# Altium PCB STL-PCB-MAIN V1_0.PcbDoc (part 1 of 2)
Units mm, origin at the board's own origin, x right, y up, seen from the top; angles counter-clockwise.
Board outline 48 x 35.2 mm, 4 copper layers (Top Layer, Int1 (GND), Int4 (PWR), Bottom Layer), stack 0.969 mm thick; 79 components, 63 nets, 420 pads, 232 vias.
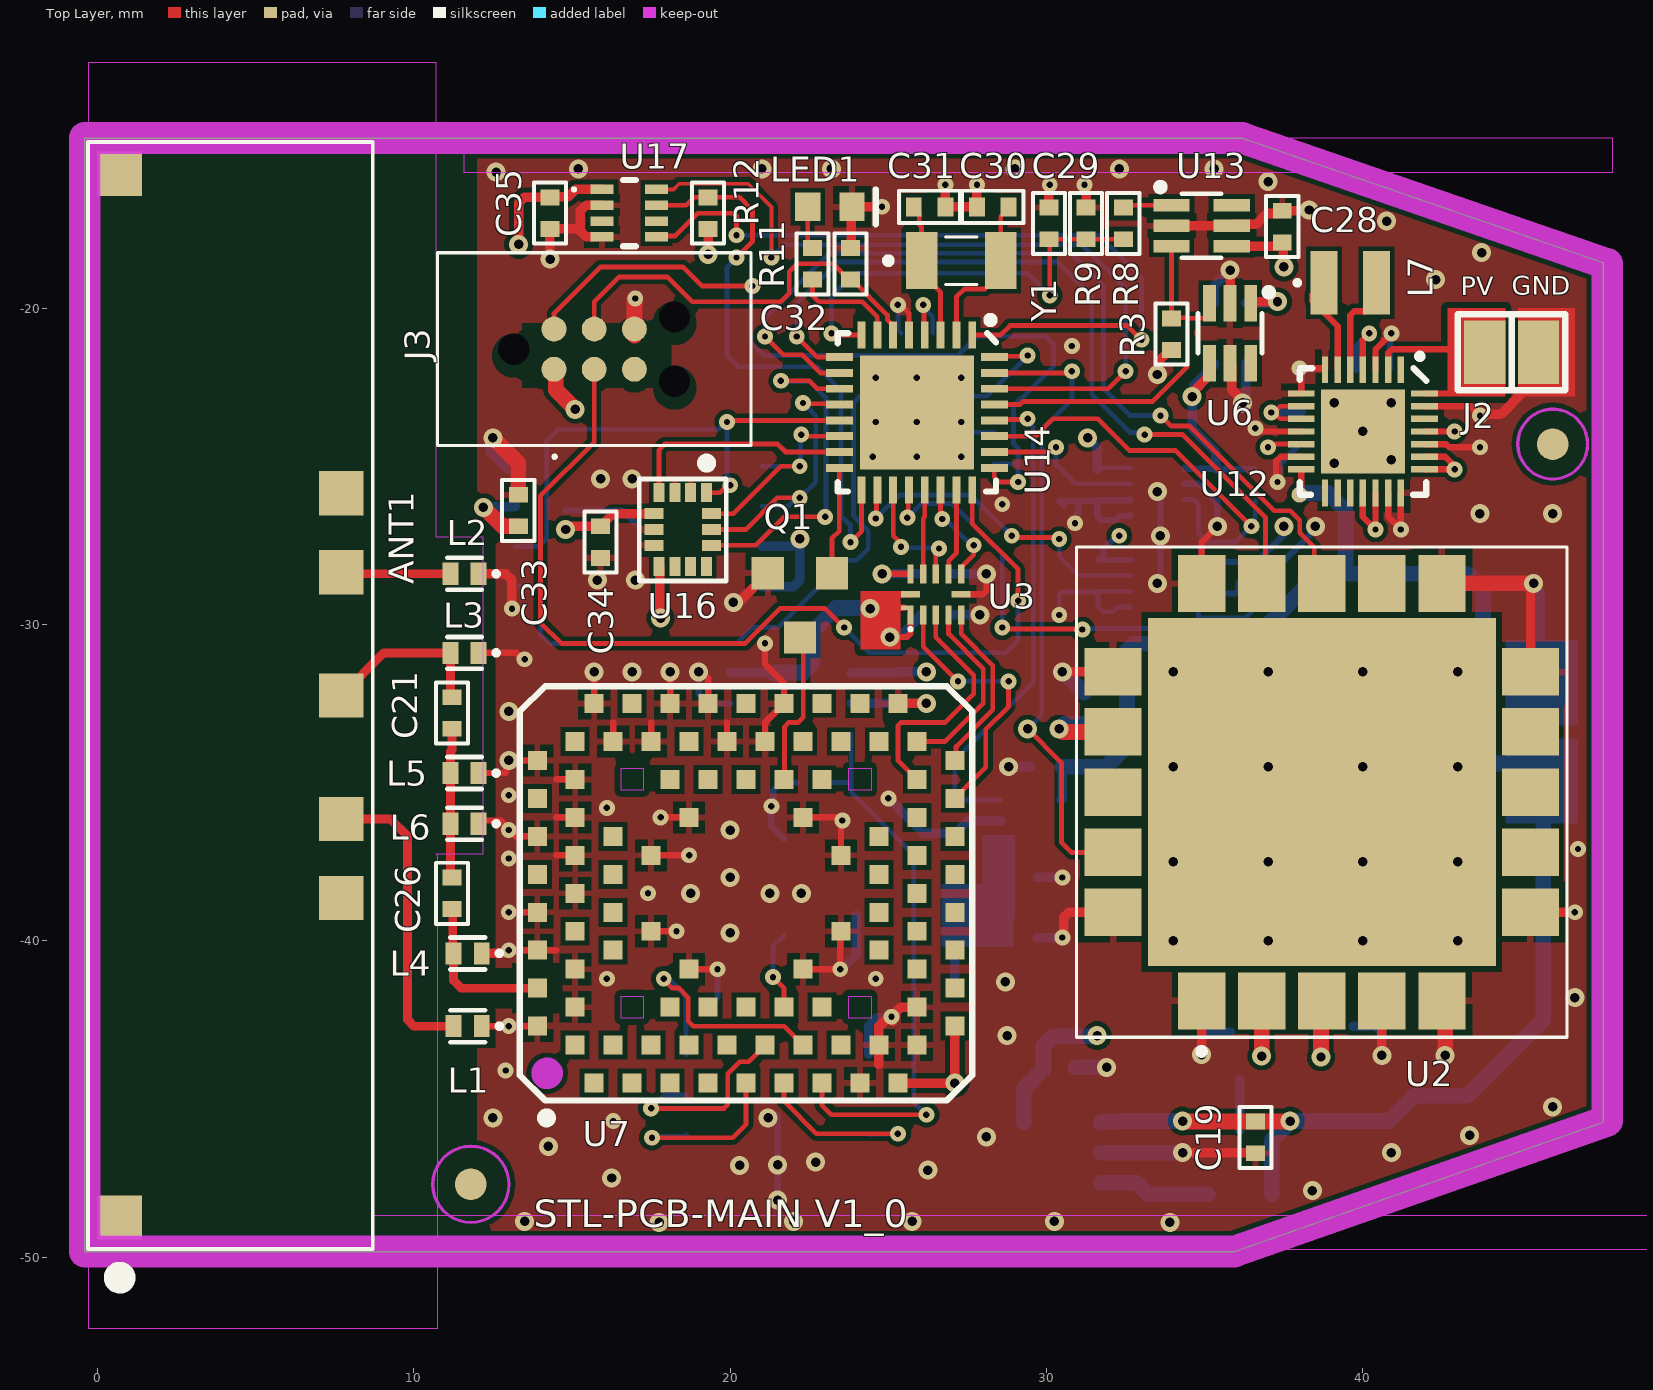
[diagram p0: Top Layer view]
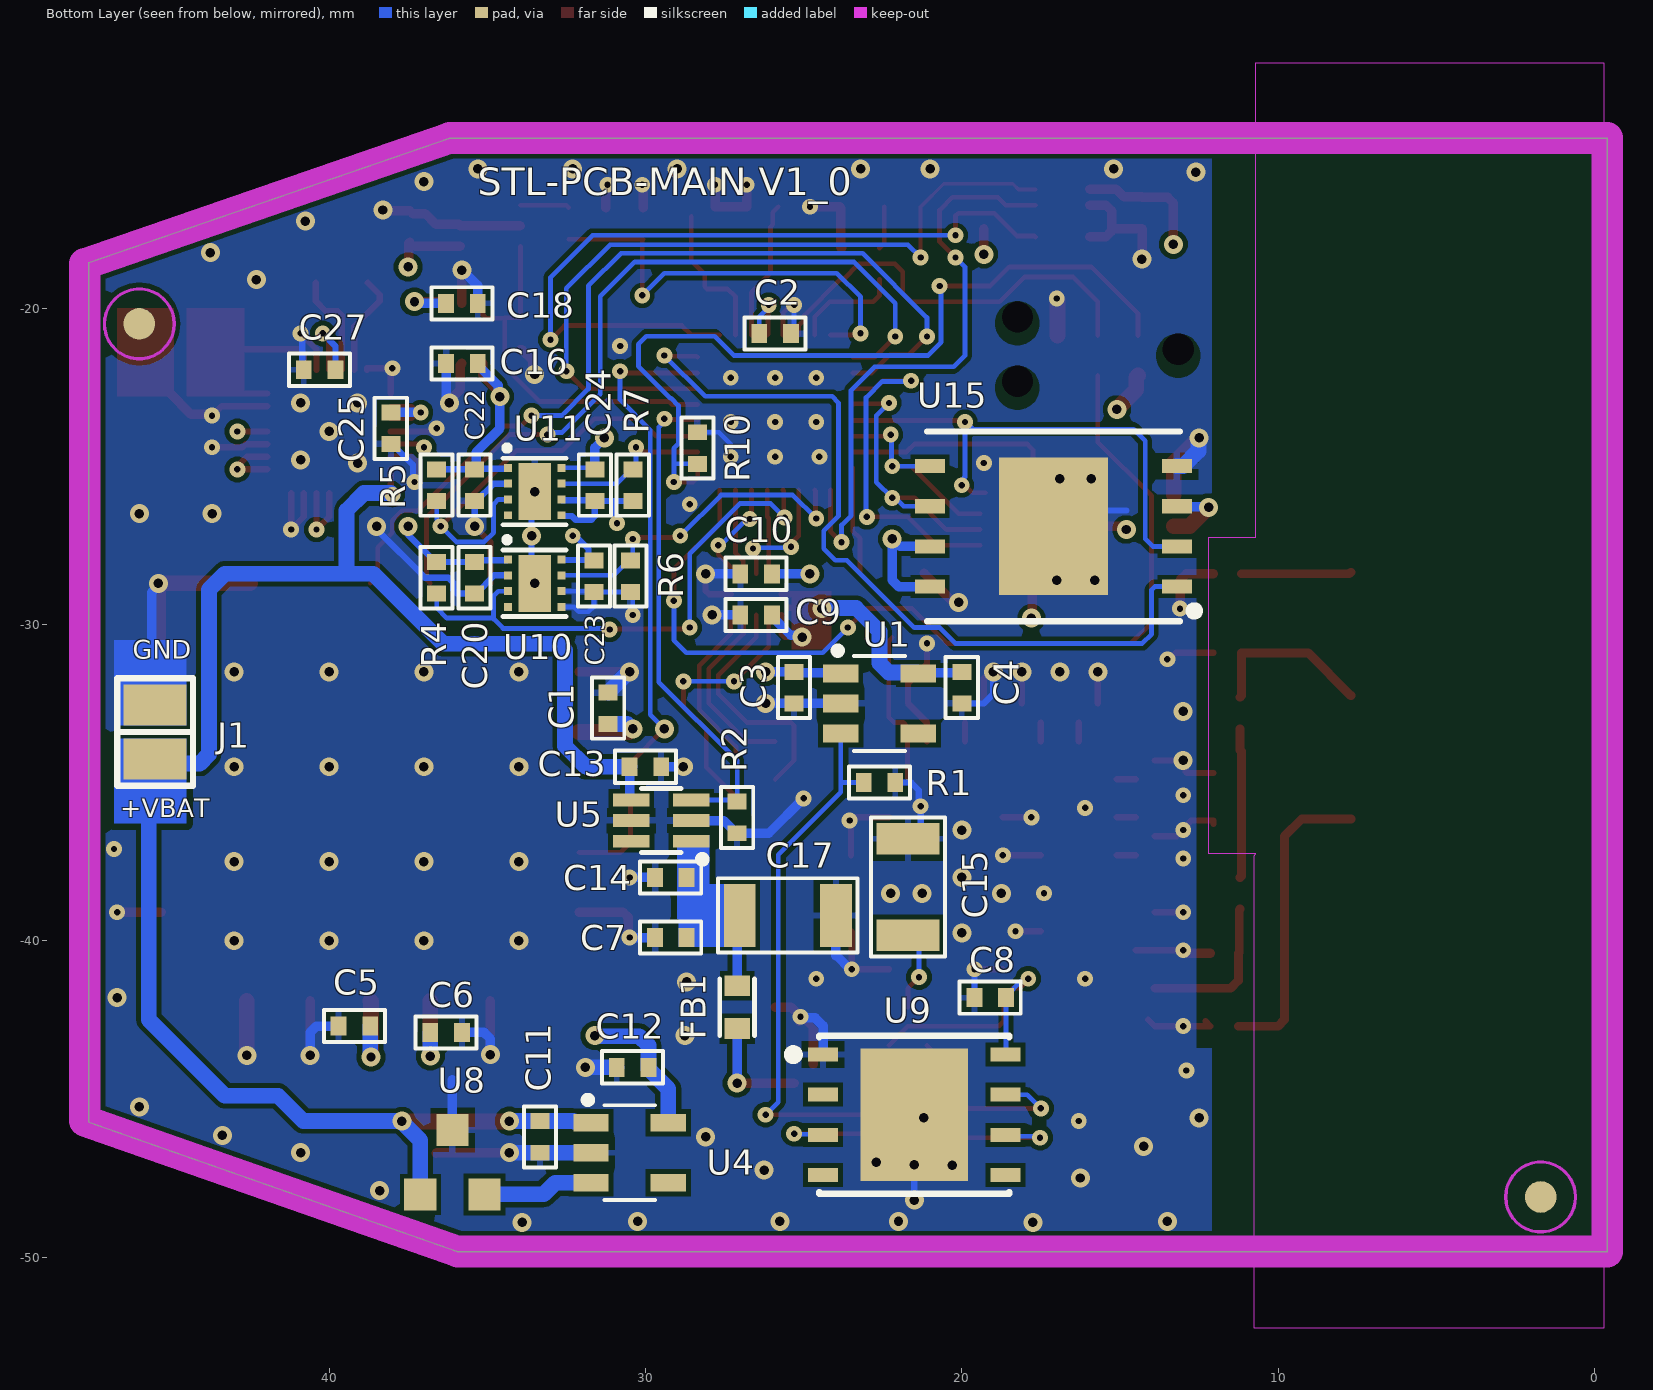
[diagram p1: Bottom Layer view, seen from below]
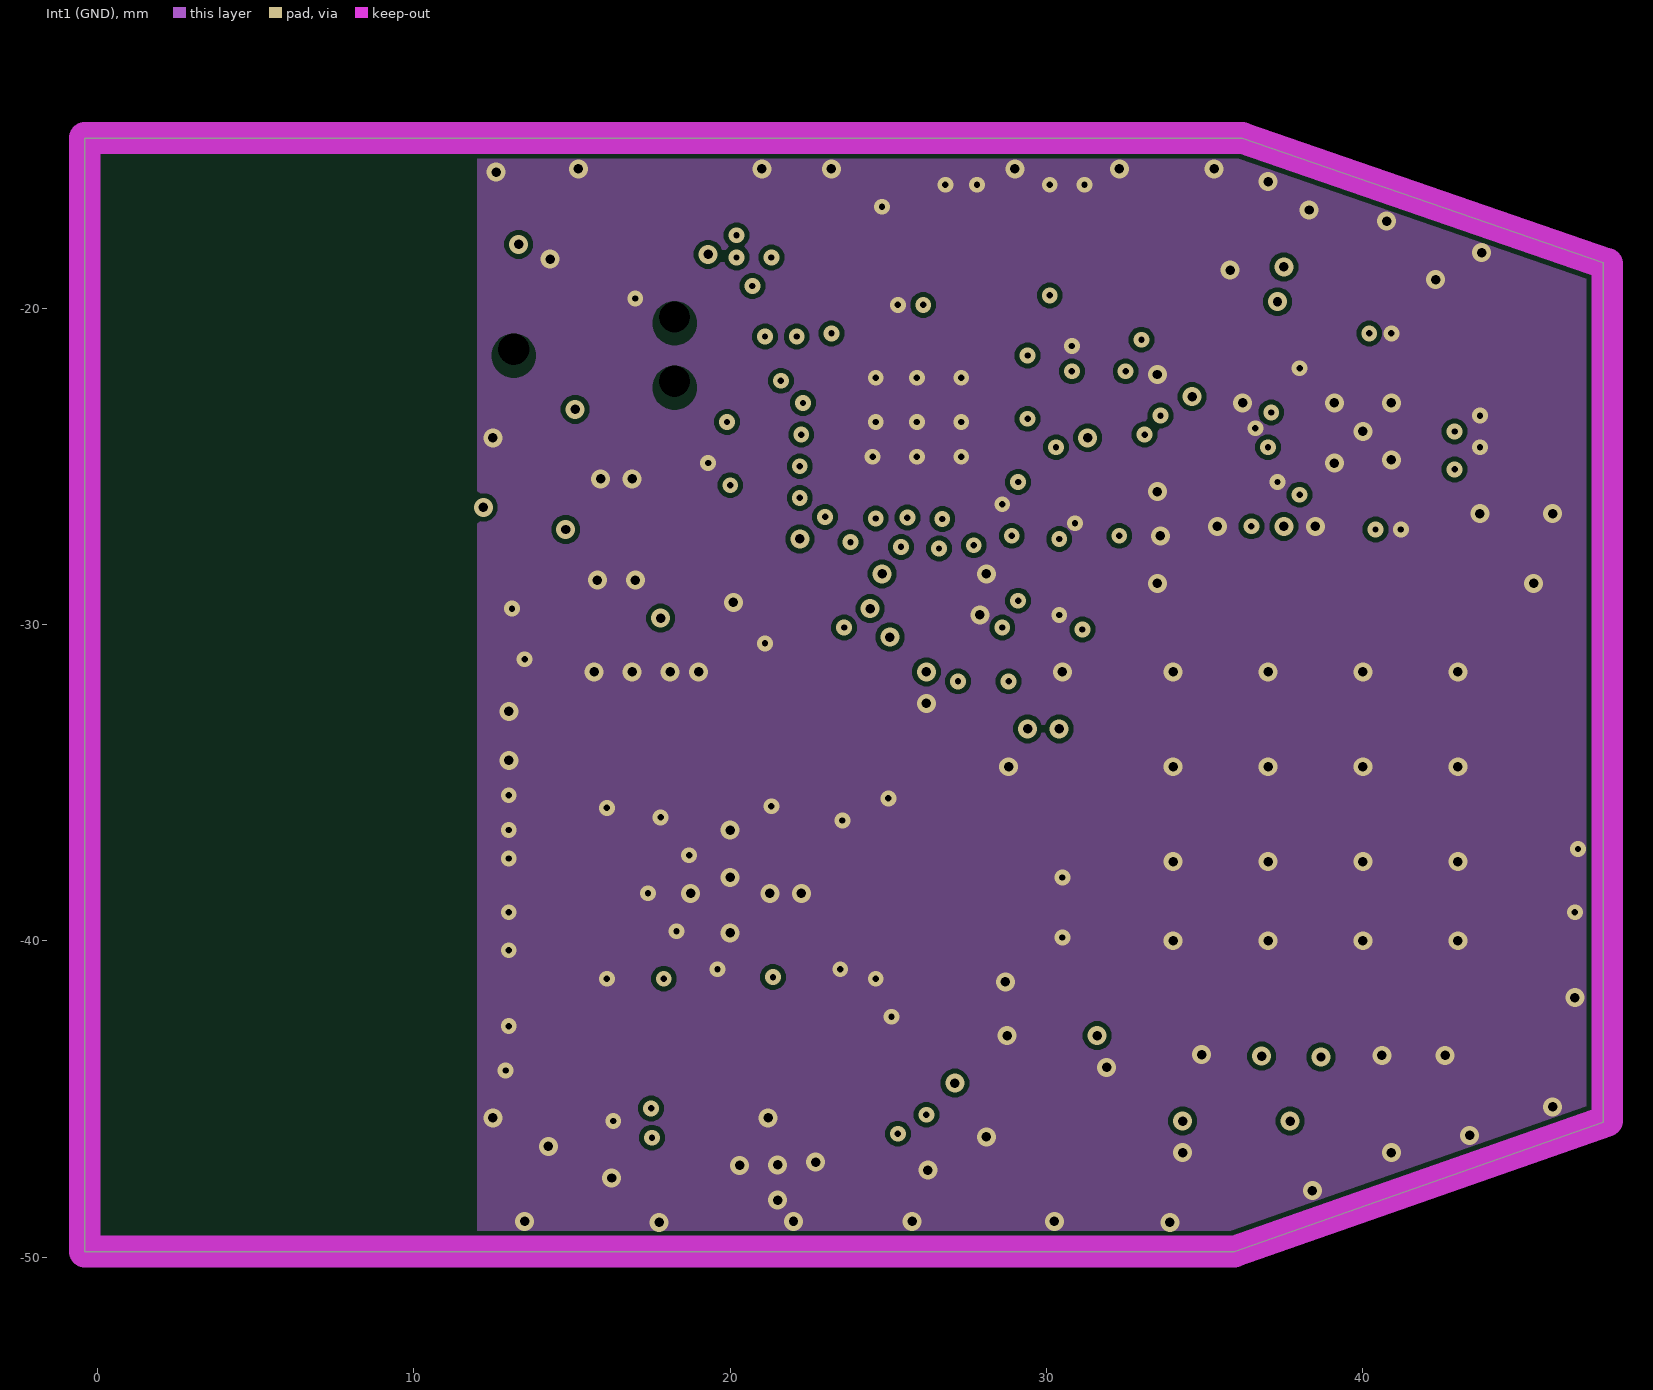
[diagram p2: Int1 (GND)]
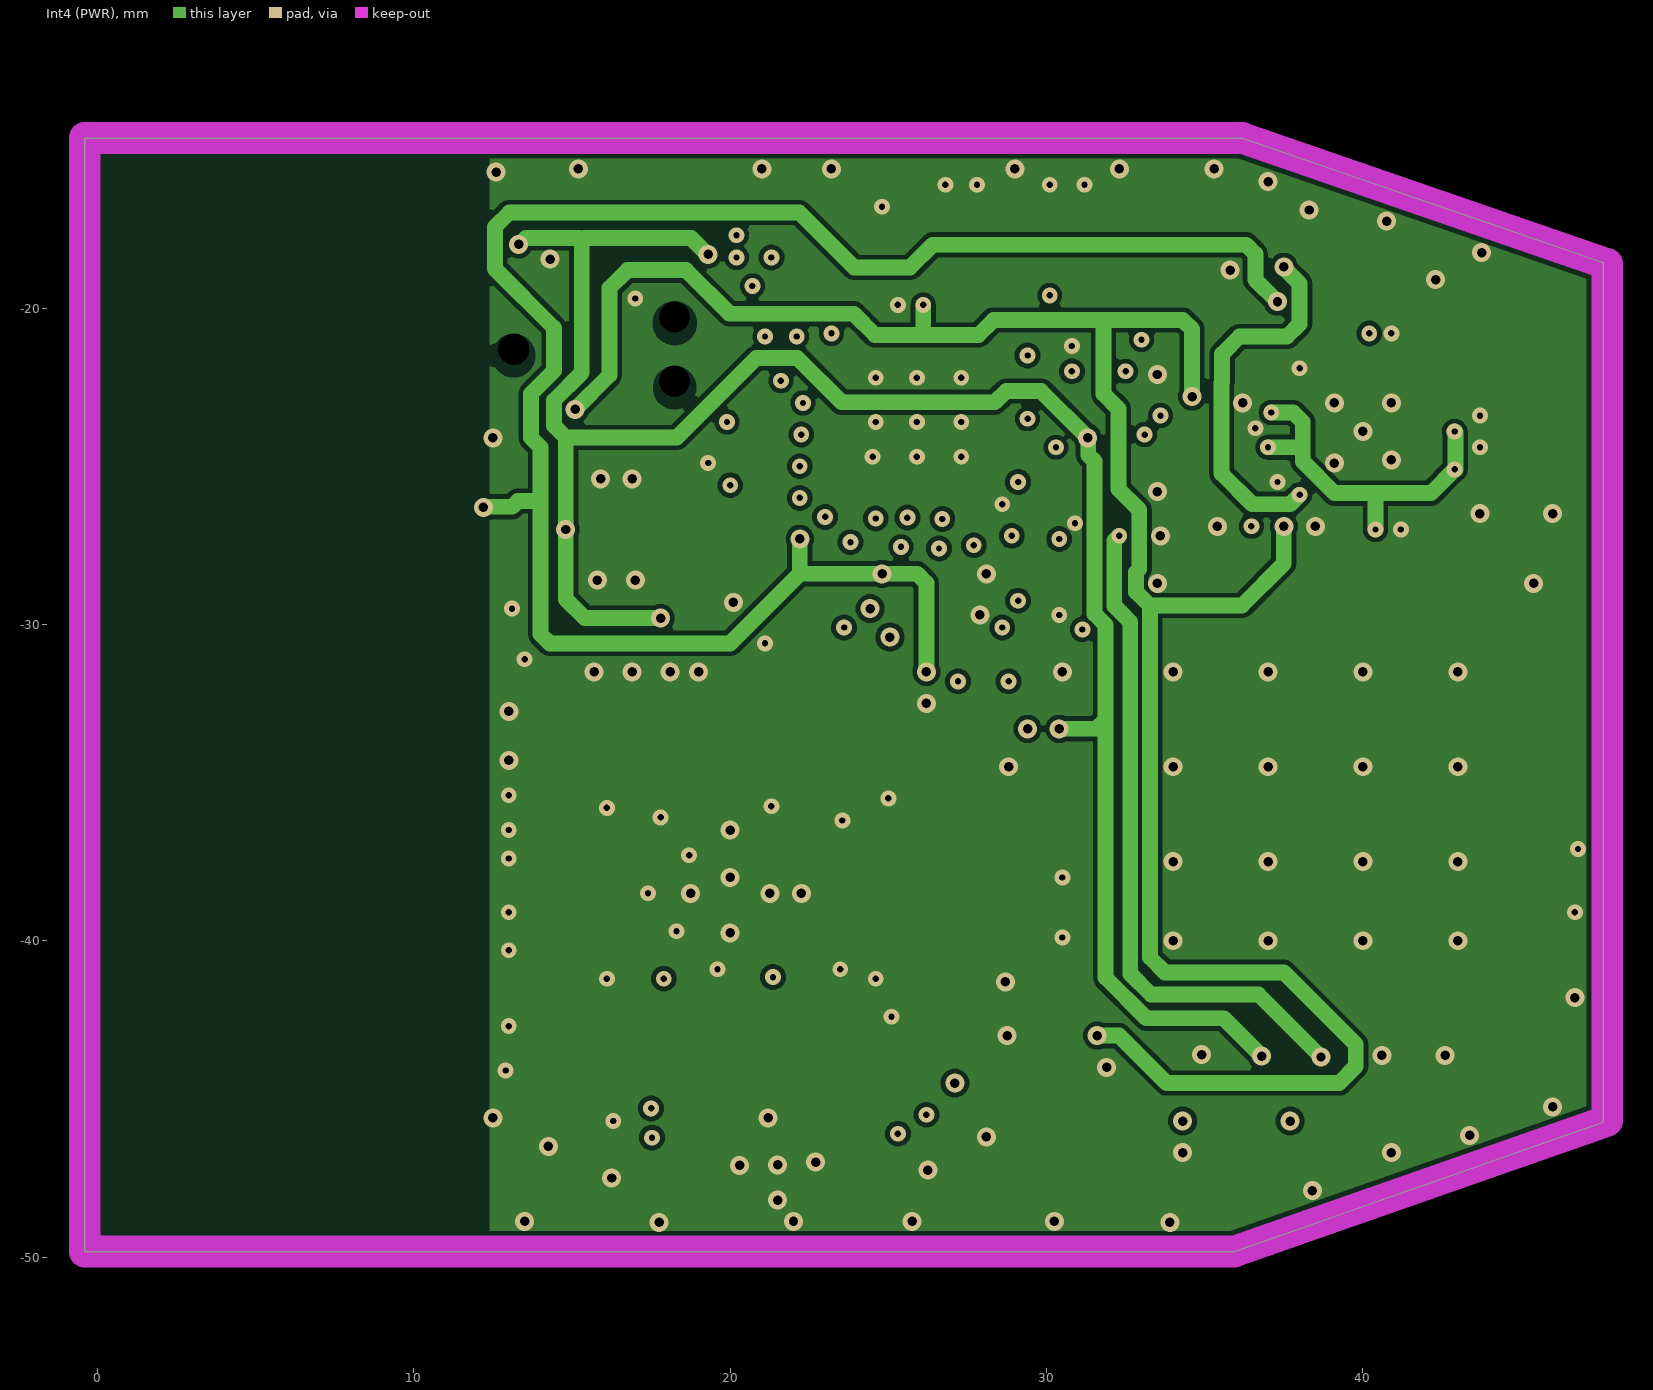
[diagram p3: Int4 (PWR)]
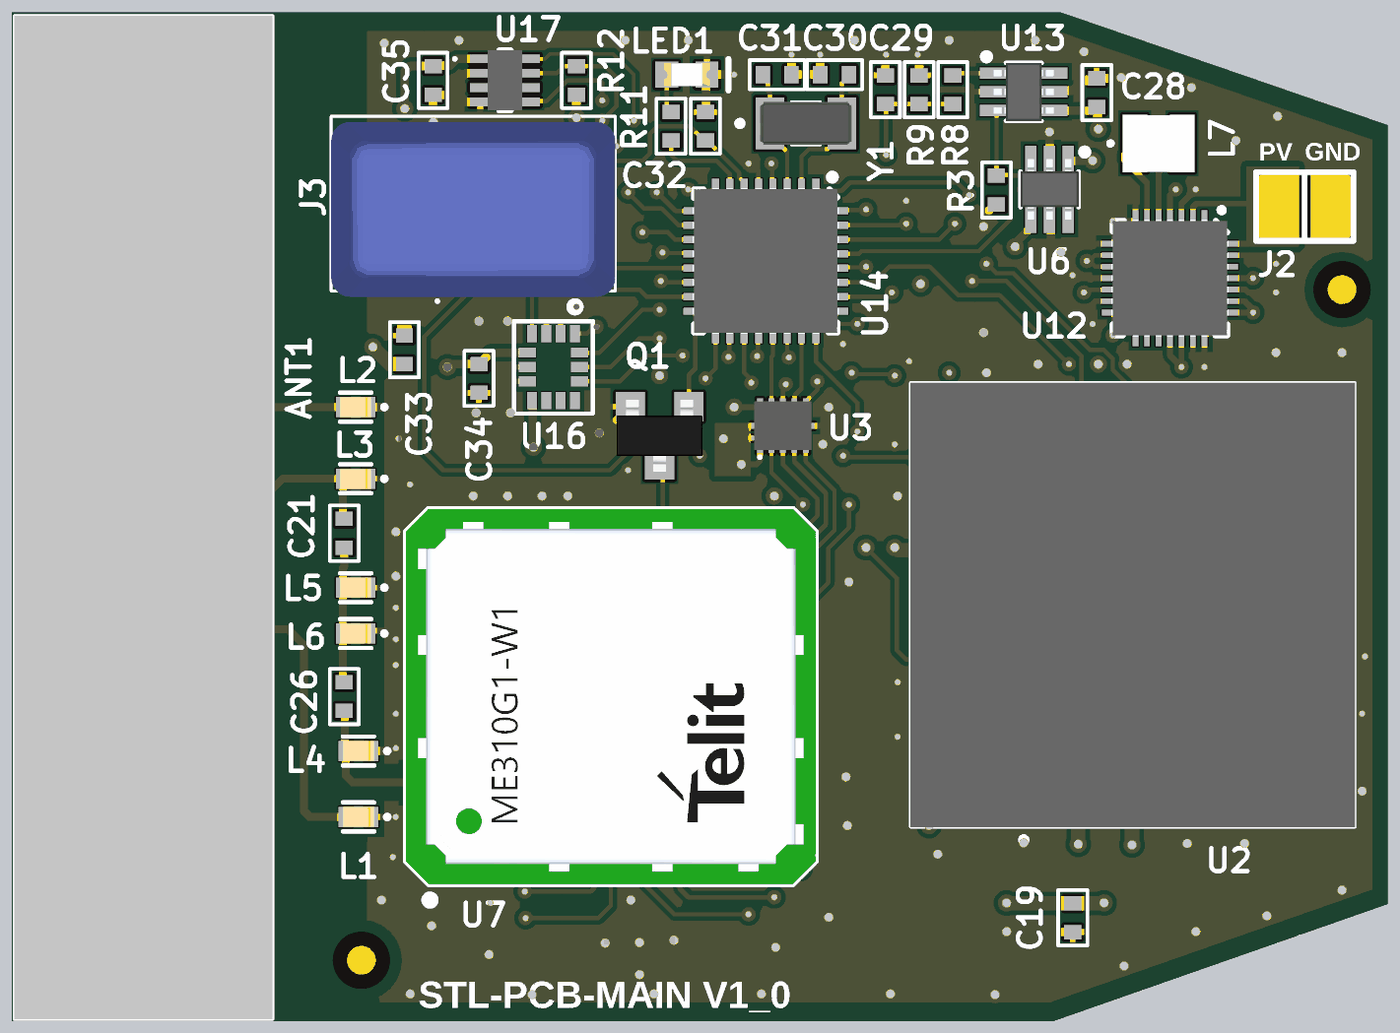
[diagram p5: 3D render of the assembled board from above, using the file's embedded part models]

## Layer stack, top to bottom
Top Solder: solder mask 0.0254, SM-001, Dk 4
Top Layer: signal copper 0.035
Dielectric 1: prepreg 0.1803, PP-021, Dk 4.7
Int1 (GND): signal copper 0.0152
Dielectric 2: core 0.508, Core-036, Dk 4.6
Int4 (PWR): signal copper 0.0152
Dielectric 3: prepreg 0.1803, PP-021, Dk 4.7
Bottom Layer: signal copper 0.035
Bottom Solder: solder mask 0.0254, SM-001, Dk 4

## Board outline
-0.4,-49.825 35.933,-49.825 47.6,-45.738 47.6,-18.565 47.599,-18.562 36.188,-14.625 -0.4,-14.625

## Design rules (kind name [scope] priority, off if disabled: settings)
BoardOutlineClearance BoardOutlineClearance_OVERLAY [OnLayer('Top Overlay')] p1: gap=0 ignorepadtopadclearanceinfootprint=FALSE
BoardOutlineClearance [All] p2: gap=0.5 ignorepadtopadclearanceinfootprint=FALSE
Clearance Clearance_GND-50ohms [InNetClass('50ohms') vs InNet('GND')] p1: gap=0.5 ignorepadtopadclearanceinfootprint=FALSE except(0.3: Arc-SMDPad Track-SMDPad SMDPad-SMDPad)
Clearance [All] p2: gap=0.2 ignorepadtopadclearanceinfootprint=FALSE except(0.12: Arc-Arc Arc-Track Arc-SMDPad Arc-Via Track-Track Track-SMDPad Track-Via; 0.14: Via-Via; 0.15: Arc-Fill Arc-Poly Arc-Region Track-Fill Track-Poly Track-Region SMDPad-SMDPad SMDPad-Via SMDPad-Fill SMDPad-Poly SMDPad-Region Via-Fill Via-Poly Via-Region; 0.254: Arc-THPad Arc-Text Track-THPad Track-Text Text-Text; 0.3: SMDPad-Text THPad-Via THPad-Text THPad-Hole Via-Text Text-Hole; 0.5: THPad-THPad)
ComponentClearance [All] p1: gap=0.25 collisioncheckmode=3 verticalgap=0.25 showdistances=FALSE
DiffPairsRouting [All] p1: maxlimit=0.25 minlimit=0.25 mostfreqgap=0.25 toplayer_minwidth=0.381 toplayer_maxwidth=0.381 toplayer_prefwidth=0.381 midlayer1_minwidth=0.381 midlayer1_maxwidth=0.381 midlayer1_prefwidth=0.381 midlayer2_minwidth=0.381 midlayer2_maxwidth=0.381 midlayer2_prefwidth=0.381 bottomlayer_minwidth=0.381 bottomlayer_maxwidth=0.381 bottomlayer_prefwidth=0.381 maxuncoupledlength=12.5
Height [All] p1: minheight=0 maxheight=40 prefheight=12.5
HoleSize HoleSize-PTH [All] p1: absolutevalues=TRUE maxlimit=3.5 minlimit=0.2 maxpercent=80.000 minpercent=20.000
HoleToHoleClearance [All] p1: gap=0.29 allowstackedmicrovias=TRUE
MinimumAnnularRing "Minimum IAR  >0.45mm" [((ObjectKind = 'Pad') OR (ObjectKind = 'Via')) And (Layer = 'MultiLayer') And (HoleDiameter > AsMM(0.45))] p1: minimumring=0.175 // minimum inner annular ring for pads > 0.45mm finished hole size
MinimumAnnularRing "Minimum IAR <=0.45mm" [((ObjectKind = 'Pad') OR (ObjectKind = 'Via')) And (Layer = 'MultiLayer') And (HoleDiameter <= AsMM(0.2))] p2: minimumring=0.074 // minimum inner annular ring for pads <= 0.45mm finished hole size
MinimumSolderMaskSliver [All] p1: minsoldermaskwidth=0.1
PlaneClearance PlaneClearance-IPI [All] p1: clearance=0.25
PlaneConnect [All] p1: planeconnectstyle=Relief reliefexpansion=0.175 reliefentries=4 reliefconductorwidth=0.2 reliefairgap=0.2
PolygonConnect PolygonConnect-FULL [InPadClass('FULL')] p1: connectstyle=Direct reliefconductorwidth=0.254 reliefentries=4 polygonreliefangle="90 Angle" airgapwidth=0.254
PolygonConnect PolygonConnect-xTW [All] p2: thpad.connectstyle=Relief thpad.reliefconductorwidth=0.3 thpad.reliefentries=4 thpad.polygonreliefangle="90 Angle" thpad.airgapwidth=0.3 smdpad.connectstyle=Relief smdpad.reliefconductorwidth=0.2 smdpad.reliefentries=4 smdpad.polygonreliefangle="90 Angle" smdpad.airgapwidth=0.2 via.connectstyle=Direct via.reliefconductorwidth=0.2 via.reliefentries=4 via.polygonreliefangle="90 Angle" via.airgapwidth=0.2
RoutingCorners [All] p1: cornerstyle=45-Degree minsetback=2.5 maxsetback=2.5
RoutingVias [All] p1: holewidth=0.2 width=0.5 viastyle="Through Hole" minholewidth=0.1 minwidth=0.25 maxholewidth=0.3 maxwidth=0.6
SilkToSilkClearance [All] p1: silktosilkclearance=0.01
SilkToSolderMaskClearance SilkscreenOverComponentPads [IsPad] p1: minsilkscreentomaskgap=0.02 clearancetoexposedcopper=TRUE
SolderMaskExpansion [All] p1: expansion=0.1 istentingtop=FALSE soldermaskfromhole=TRUE
UnRoutedNet [All] p1: checkbadconnections=TRUE
Width Width_50ohms [InNetClass('50ohms')] p1: maxlimit=1 minlimit=0.278 preferedwidth=1 toplayer_maxwidth=0.278 toplayer_prefwidth=0.278 midlayer1_minwidth=1 midlayer2_minwidth=1 bottomlayer_maxwidth=0.278 bottomlayer_prefwidth=0.278 minimp=50.000000 maximp=50.000000 favimp=50.000000
Width [All] p2: maxlimit=1 minlimit=0.12 preferedwidth=0.15
18 further rules are at their usual default settings.

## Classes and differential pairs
component class 4-Capteurs: C34 C35 R12 U16 U17
component class 2-Micro: C2 C28 C29 C30 C31 C32 C33 J3 LED1 Q1 R8 R9 R10 R11 U13 U14 U15 Y1
pad class FULL: U4-5 U9-9 U15-9
net class 50ohms: ANT NetANT1_3 NetANT1_4 NetANT1_5 NetC21_2
component class 1-Alim: C11 C12 C13 C14 C16 C18 C19 C20 C22 C23 C24 C25 C27 J1 J2 L7 R2 R3 R4 R5 R6 R7 U4 U5 U6 U8 U10 U11 U12
component class 3-Modules: ANT1 C1 C3 C4 C5 C6 C7 C8 C9 C10 C15 C17 C21 C26 FB1 L1 L2 L3 L4 L5 L6 R1 U1 U2 U3 U7 U9

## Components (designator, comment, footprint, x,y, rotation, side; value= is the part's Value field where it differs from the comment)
ANT1 "LSP69001299TR" ANT-LSP69001299TR 4.2,-32.25 r90 top locked
C1 "100nF" CAP_0402_0H80 31.177,-32.65 r270 bottom
C2 "100nF" CAP_0402_0H80 25.9,-20.8 r0 bottom
C3 "22µF" CAP_0402_0H80 25.3,-32 r90 bottom
C4 "22µF" CAP_0402_0H80 20,-32 r90 bottom
C5 "100nF" CAP_0402_0H80 39.2,-42.7 r180 bottom
C6 "100nF" CAP_0402_0H80 36.3,-42.9 r0 bottom
C7 "100nF" CAP_0402_0H80 29.2,-39.9 r180 bottom
C8 "100nF" CAP_0402_0H80 19.1,-41.8 r180 bottom
C9 "100nF" CAP_0402_0H80 26.5,-29.7 r0 bottom
C10 "100nF" CAP_0402_0H80 26.5,-28.4 r180 bottom
C11 "22µF" CAP_0402_0H80 33.329,-46.2 r90 bottom
C12 "22µF" CAP_0402_0H80 30.404,-44 r180 bottom
C13 "22µF" CAP_0402_0H80 30,-34.5 r0 bottom
C14 "22µF" CAP_0402_0H80 29.2,-38 r180 bottom
C15 "C1206C107M9PACTU" CAP_1206_1H90 21.7,-38.3 r270 bottom
C16 "22µF" CAP_0402_0H80 35.8,-21.75 r180 bottom
C17 "C1206C107M9PACTU" CAP_1206_1H90 25.5,-39.2 r0 bottom
C18 "22µF" CAP_0402_0H80 35.8,-19.85 r0 bottom
C19 "100nF" CAP_0402_0H80 36.608,-46.218 r90 top
C20 "22µF" CAP_0402_0H80 35.4,-28.525 r90 bottom
C21 "1.2pF" CAP_0402_0H80 11.2,-32.8 r270 top
C22 "22µF" CAP_0402_0H80 35.4,-25.6 r90 bottom
C23 "22µF" CAP_0402_0H80 31.625,-28.475 r90 bottom
C24 "22µF" CAP_0402_0H80 31.6,-25.6 r90 bottom
C25 "22µF" CAP_0402_0H80 38.05,-23.8 r90 bottom
C26 "33pF" CAP_0402_0H80 11.2,-38.5 r270 top
C27 "15µF" CAP_0402_0H80 40.3,-21.95 r180 bottom
C28 "22µF" CAP_0402_0H80 37.45,-17.425 r270 top
C29 "100nF" CAP_0402_0H80 30.075,-17.325 r270 top
C30 "6.8pF" CAP_0402_0H80 28.3,-16.8 r180 top
C31 "6.8pF" CAP_0402_0H80 26.3,-16.8 r0 top
C32 "100nF" CAP_0402_0H80 23.8,-18.6 r90 top
C33 "100nF" CAP_0402_0H80 13.3,-26.4 r270 top
C34 "100nF" CAP_0402_0H80 15.9,-27.4 r90 top
C35 "100nF" CAP_0402_0H80 14.3,-17 r90 top
FB1 "BLM18EG221SN1D" BLM18EG101TN1B 27.1,-42.1 r90 bottom
J1 "Header 2" 2PLAGES-2X1.3mm 45.5,-33.4 r90 bottom
J2 "Header 2" 2PLAGES-2X1.3mm 44.7,-21.4 r0 top
J3 "TC2030 NL" TC2030MCPNL10 15.7,-21.5 r0 top
L1 "LQW15AN20NG00D" IND_LQW15AN 11.7,-42.7 r180 top
L2 "LQW15AN20NG00D" IND_LQW15AN 11.6,-28.4 r180 top
L3 "LQW15AN22NG00D" IND_LQW15AN 11.6,-30.9 r180 top
L4 "LQW15AN20NG00D" IND_LQW15AN 11.7,-40.4 r180 top
L5 "LQW15AN20NG00D" IND_LQW15AN 11.6,-34.7 r180 top
L6 "LQW15AN20NG00D" IND_LQW15AN 11.6,-36.3 r180 top
L7 "MURATA-1.5µH-3.8A-2.5x2x1.2" VLS2520 39.6,-19.2 r0 top value=10uH
LED1 "TLMS1100-GS08" LED_150060VS7500 23.2,-16.8 r180 top
Q1 "SI2302CDS-T1-GE3" SOT23 22.2,-29.4 r0 top
R1 "100k" RES_0402_0H65 22.6,-35 r0 bottom
R2 "100k" RES_0402_0H65 27.1,-36.1 r90 bottom
R3 "100k" RES_0402_0H65 33.95,-20.825 r90 top
R4 "100k" RES_0402_0H65 36.6,-28.525 r90 bottom
R5 "100k" RES_0402_0H65 36.6,-25.6 r90 bottom
R6 "100k" RES_0402_0H65 30.475,-28.475 r90 bottom
R7 "100k" RES_0402_0H65 30.4,-25.6 r90 bottom
R8 "54k" RES_0402_0H65 32.425,-17.325 r90 top
R9 "200k" RES_0402_0H65 31.25,-17.325 r270 top
R10 "100k" RES_0402_0H65 28.35,-24.425 r90 bottom
R11 "1k" RES_0402_0H65 22.6,-18.6 r270 top
R12 "100k" RES_0402_0H65 19.3,-17 r270 top
U1 "TPS7A0230PDBVR" TPS7A0230PDBVR-SOT23-5 22.6,-32.5 r270 bottom
U2 "SAM-M8Q-0-10" SAMM8Q010 38.7,-35.3 r90 top
U3 "TXB0104RUTR" TXB0104RUTR 26.5,-29.05 r0 top
U4 "TPS7A0230PDBVR" TPS7A0230PDBVR-SOT23-5 30.5,-46.7 r270 bottom
U5 "SIP32431DR3-T1GE3" SIP32431DR3-T1GE3 29.5,-36.2 r0 bottom
U6 "SIP32431DR3-T1GE3" SIP32431DR3-T1GE3 35.8,-20.8 r270 top
U7 "ME310G1-W1" ME310G1-W1 20.5,-38.5 r90 top
U8 "SM353LT" SOT23 36.1,-47 r0 bottom
U9 "eSIM" ST4SI2M0020TPIFW 21.5,-45.5 r180 bottom
U10 "XC6194B1NNER-G" XC6194B1NNER-G 33.5,-28.7 r270 bottom
U11 "XC6194B1NNER-G" XC6194B1NNER-G 33.5,-25.8 r270 bottom
U12 "aem10300" AEM10300-QFN28-4X4mm 40,-23.9 r270 top
U13 "SIP32431DR3-T1GE3" SIP32431DR3-T1GE3 34.9,-17.4 r0 top
U14 "STM32G0B1KEU6" STM32G0B1KEU6 25.9,-23.3 r270 top
U15 "W25N02KVZEIR" W25N02KVZEIR 17.1,-26.9 r0 bottom
U16 "LSM6DS3TR" LSM6DSOTR-LGA14 18.5,-27 r270 top
U17 "OPT3005DTSR" OPT3005DTSR 16.81,-17 r0 top
Y1 "NX3215SA-32.768K-EXS00A-MU00003" NX3215SA 27.3,-18.5 r0 top

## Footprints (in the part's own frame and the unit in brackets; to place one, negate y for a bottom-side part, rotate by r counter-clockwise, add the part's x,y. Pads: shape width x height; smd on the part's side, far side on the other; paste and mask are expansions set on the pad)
2PLAGES-2X1.3mm [mm]
  rect 1.3x2 smd paste-3 mask+0.1: 1(-0.85,0) 2(0.85,0)
  silkscreen extent -1.7,-1.2 1.7,1.2
AEM10300-QFN28-4X4mm [mm]
  rect 0.85x0.2 smd mask+0.05: 1(-1.95,1.2) 2(-1.95,0.8) 3(-1.95,0.4) 4(-1.95,0) 5(-1.95,-0.4) 6(-1.95,-0.8) 7(-1.95,-1.2) 15(1.95,-1.2) 16(1.95,-0.8) 17(1.95,-0.4) 18(1.95,0) 19(1.95,0.4) 20(1.95,0.8) 21(1.95,1.2)
  rect 0.2x0.85 smd mask+0.05: 8(-1.2,-1.95) 9(-0.8,-1.95) 10(-0.4,-1.95) 11(0,-1.95) 12(0.4,-1.95) 13(0.8,-1.95) 14(1.2,-1.95) 22(1.2,1.95) 23(0.8,1.95) 24(0.4,1.95) 25(0,1.95) 26(-0.4,1.95) 27(-0.8,1.95) 28(-1.2,1.95)
  rect 2.65x2.65 smd mask+0.05: 29(0,0)
  silkscreen extent -2.45,-2 2,2, body extent -2.05,-2.05 2.05,2.05, height 0.85
ANT-LSP69001299TR [mm]
  rect 1.4x1.4 smd: 1(-16.5,3.5) 2(-6.402,-3.5) 3(-3.9,-3.5) 4(0,-3.5) 5(3.9,-3.5) 6(6.4,-3.5) 7(16.5,3.5)
  Top Layer keep-out region: -20,4.5 -20,-6.556 -5.056,-6.556 -5,-6.5 -5,-8 5,-8 5,-6.5 19.992,-6.5 20,-6.508 20,4.5 20,4.5
  Bottom Layer keep-out region: -20,4.5 -20,-6.556 -5.056,-6.556 -5,-6.5 -5,-8 5,-8 5,-6.5 19.992,-6.5 20,-6.508 20,4.5 20,4.5
  silkscreen extent -18.65,-4.5 17.5,4.5, body extent -17.5,-4.5 17.5,4.5, height 3.17
BLM18EG101TN1B [mm]
  rect 0.65x0.8 smd: 1(-0.675,0) 2(0.675,0)
  silkscreen extent -0.9,-0.55 0.9,0.55, body extent -0.9,-0.5 0.9,0.5, height 0.65
CAP_0402_0H80 [mm]
  rect 0.5x0.6 smd: 1(-0.5,0) 2(0.5,0)
  silkscreen extent -0.97,-0.51 0.97,0.51, body extent -0.5,-0.25 0.5,0.25, height 0.8
CAP_1206_1H90 [mm] "refusion"
  rect 1x2 smd paste+0 mask+0.1: 1(-1.524,0) 2(1.524,0)
  silkscreen extent -2.2,-1.17 2.2,1.17, body extent -1.6,-0.8 1.6,0.8, height 1.9
IND_LQW15AN [mm]
  rect 0.5x0.7 smd paste+0 mask+0.05: 1(-0.445,0) 2(0.445,0)
  silkscreen extent -1.05,-0.51 0.55,0.51, body extent -0.55,-0.36 0.55,0.36, height 0.61
LED_150060VS7500 [mm]
  rect 0.8x0.9 smd: 1(-0.65,0) 2(0.75,0)
  silkscreen extent -1.4,-0.55 -1.4,0.55, body extent -0.75,-0.4 0.85,0.4, height 0.7
LSM6DSOTR-LGA14 [mm] "2.5X3.0X0.86"
  rect 0.6x0.35 smd mask+0.025: 1(-1.162,0.75) 2(-1.162,0.25) 3(-1.162,-0.25) 4(-1.162,-0.75) 8(1.162,-0.75) 9(1.162,-0.25) 10(1.162,0.25) 11(1.162,0.75)
  rect 0.35x0.6 smd mask+0.025: 5(-0.5,-0.913) 6(0,-0.913) 7(0.5,-0.913) 12(0.5,0.913) 13(0,0.913) 14(-0.5,0.913)
  silkscreen extent -2.2,-1.38 1.63,1.38, body extent -1.55,-1.3 1.55,1.3, height 0.87
ME310G1-W1 [mm]
  rect 0.6x0.6 smd mask+0.1: A3(-4.2,6.6) A5(-3,6.6) A7(-1.8,6.6) A9(-0.6,6.6) A11(0.6,6.6) A13(1.8,6.6) A15(3,6.6) A17(4.2,6.6) AA3(-4.2,-6.6) AA5(-3,-6.6) AA7(-1.8,-6.6) AA9(-0.6,-6.6) AA11(0.6,-6.6) AA13(1.8,-6.6) AA15(3,-6.6) AA17(4.2,-6.6) B2(-4.8,5.4) B4(-3.6,5.4) B6(-2.4,5.4) B8(-1.2,5.4) B10(0,5.4) B12(1.2,5.4) B14(2.4,5.4) B16(3.6,5.4) B18(4.8,5.4) C1(-6,4.8) C19(6,4.8) D2(-4.8,4.2) D7(-1.8,4.2) D9(-0.6,4.2) D11(0.6,4.2) D13(1.8,4.2) D18(4.8,4.2) E1(-6,3.6) E19(6,3.6) F2(-4.8,3) F8(-1.2,3) F12(1.2,3) F18(4.8,3) G1(-6,2.4) G4(-3.6,2.4) G16(3.6,2.4) G19(6,2.4) H2(-4.8,1.8) H6(-2.4,1.8) H14(2.4,1.8) H18(4.8,1.8) J1(-6,1.2) J4(-3.6,1.2) J16(3.6,1.2) J19(6,1.2) K2(-4.8,0.6) K18(4.8,0.6) L1(-6,0) L4(-3.6,0) L16(3.6,0) L19(6,0) M2(-4.8,-0.6) M18(4.8,-0.6) N1(-6,-1.2) N4(-3.6,-1.2) N16(3.6,-1.2) N19(6,-1.2) P2(-4.8,-1.8) P6(-2.4,-1.8) P14(2.4,-1.8) P18(4.8,-1.8) R1(-6,-2.4) R4(-3.6,-2.4) R16(3.6,-2.4) R19(6,-2.4) T2(-4.8,-3) T8(-1.2,-3) T12(1.2,-3) T18(4.8,-3) U1(-6,-3.6) U19(6,-3.6) V2(-4.8,-4.2) V7(-1.8,-4.2) V9(-0.6,-4.2) V11(0.6,-4.2) V13(1.8,-4.2) V18(4.8,-4.2) W1(-6,-4.8) W19(6,-4.8) Y2(-4.8,-5.4) Y4(-3.6,-5.4) Y6(-2.4,-5.4) Y8(-1.2,-5.4) Y10(0,-5.4) Y12(1.2,-5.4) Y14(2.4,-5.4) Y16(3.6,-5.4) Y18(4.8,-5.4)
  Top Layer keep-out circle w0.5: c-5.69,6.29 r0.25
  Top Layer keep-out region: -3.25,-3.95 -3.95,-3.95 -3.95,-3.25 -3.25,-3.25
  Top Layer keep-out region: -3.25,3.25 -3.95,3.25 -3.95,3.95 -3.25,3.95
  Top Layer keep-out region: 3.95,3.25 3.25,3.25 3.25,3.95 3.95,3.95
  Top Layer keep-out region: 3.95,-3.95 3.25,-3.95 3.25,-3.25 3.95,-3.25
  silkscreen extent -7.25,-7.15 6.55,7.15, body extent -6.55,-7.15 6.55,7.15, height 2.6
NX3215SA [mm]
  rect 1x1.8 smd: 1(-1.25,0) 2(1.25,0)
  silkscreen extent -2.4,-0.75 0.5,0.75, body extent -1.6,-0.75 1.6,0.75, height 0.8
OPT3005DTSR [mm]
  rect 0.72x0.3 smd: 1(-0.86,0.75) 2(-0.86,0.25) 3(-0.86,-0.25) 4(-0.86,-0.75) 5(0.86,-0.75) 6(0.86,-0.25) 7(0.86,0.25) 8(0.86,0.75)
  silkscreen extent -1.8,-1.05 0.2,1.05, body extent -0.6,-1.05 0.6,1.05, height 0.7
RES_0402_0H65 [mm]
  rect 0.5x0.6 smd: 1(-0.5,0) 2(0.5,0)
  silkscreen extent -0.97,-0.51 0.97,0.51, body extent -0.5,-0.25 0.5,0.25, height 0.65
SAMM8Q010 [mm]
  rect 1.8x1.5 smd: 1(-6.6,3.8) 2(-6.6,1.9) 3(-6.6,0) 4(-6.6,-1.9) 5(-6.6,-3.8) 11(6.6,-3.8) 12(6.6,-1.9) 13(6.6,0) 14(6.6,1.9) 15(6.6,3.8)
  rect 1.5x1.8 smd: 6(-3.8,-6.6) 7(-1.9,-6.6) 8(0,-6.6) 9(1.9,-6.6) 10(3.8,-6.6) 16(3.8,6.6) 17(1.9,6.6) 18(0,6.6) 19(-1.9,6.6) 20(-3.8,6.6)
  rect 11x11 smd: 21(0,0)
  silkscreen extent -8.3,-7.75 7.75,7.75, body extent -7.75,-7.75 7.75,7.75, height 3.1
SIP32431DR3-T1GE3 [mm] "SC70-6"
  rect 1.15x0.4 smd mask+0.05: 1(-0.95,0.65) 2(-0.95,0) 3(-0.95,-0.65) 4(0.95,-0.65) 5(0.95,0) 6(0.95,0.65)
  silkscreen extent -1.38,-1.01 0.63,1.3, body extent -1.05,-1.01 1.05,1.01, height 1.1
SOT23 [mil]
  rect 40x40 smd: 1(40,40) 2(-40,40) 3(0,-40)
  body extent -59,-49 59,49, height 43
ST4SI2M0020TPIFW [mm]
  rect 0.94x0.44 smd mask+0.05: 1(-2.885,1.905) 2(-2.885,0.635) 3(-2.885,-0.635) 4(-2.885,-1.905) 5(2.885,-1.905) 6(2.885,-0.635) 7(2.885,0.635) 8(2.885,1.905)
  rect 3.4x4.2 smd paste-3 mask+0.05: 9(0,0)
  silkscreen extent -3.98,-2.5 3,2.5, body extent -3,-2.5 3,2.5, height 1.01
STM32G0B1KEU6 [mm] "QFPN32-5X5mm"
  rect 0.85x0.25 smd mask+0.038: 1(-2.45,1.75) 8(-2.45,-1.75) 17(2.45,-1.75) 24(2.45,1.75)
  rect 0.85x0.25 smd mask+0.05: 2(-2.45,1.25) 3(-2.45,0.75) 4(-2.45,0.25) 5(-2.45,-0.25) 6(-2.45,-0.75) 7(-2.45,-1.25) 18(2.45,-1.25) 19(2.45,-0.75) 20(2.45,-0.25) 21(2.45,0.25) 22(2.45,0.75) 23(2.45,1.25)
  rect 0.25x0.85 smd mask+0.038: 9(-1.75,-2.45) 16(1.75,-2.45) 25(1.75,2.45) 32(-1.75,2.45)
  rect 0.25x0.85 smd mask+0.05: 10(-1.25,-2.45) 11(-0.75,-2.45) 12(-0.25,-2.45) 13(0.25,-2.45) 14(0.75,-2.45) 15(1.25,-2.45) 26(1.25,2.45) 27(0.75,2.45) 28(0.25,2.45) 29(-0.25,2.45) 30(-0.75,2.45) 31(-1.25,2.45)
  rect 3.6x3.6 smd mask+0.05: 33(0,0)
  silkscreen extent -3.02,-2.5 2.5,2.5, body extent -2.55,-2.55 2.55,2.55, height 0.6
TC2030MCPNL10 [mm]
  round 0.787 smd: 1(-1.27,-0.434) 2(-1.27,0.836) 3(0,-0.434) 4(0,0.836) 5(1.27,-0.434) 6(1.27,0.836)
  round 0.495 hole 0.991 unplated: 7(-2.54,0.201) 8(2.54,1.217) 9(2.54,-0.815)
  silkscreen extent -4.95,-3.25 4.95,3.25, body extent -4.95,-3.05 4.95,3.05, height 25.67
TPS7A0230PDBVR-SOT23-5 [mil] "refusion"
  rect 22x44 smd paste+0 mask+3.94: 1(-37.4,-48.11) 2(0,-48.11) 3(37.4,-48.11) 4(37.4,48.11) 5(-37.4,48.11)
  silkscreen extent -70,-56 59,31, body extent -59,-49 59,49, height 43
TXB0104RUTR [mm]
  rect 0.2x0.6 smd: 1(-0.8,-0.65) 2(-0.4,-0.65) 3(0,-0.65) 4(0.4,-0.65) 5(0.8,-0.65) 7(0.8,0.65) 8(0.4,0.65) 9(0,0.65) 10(-0.4,0.65) 11(-0.8,0.65)
  rect 0.6x0.2 smd: 6(0.8,0) 12(-0.8,0)
  rect 0.2x0.15 smd: 13(-1,-0.425)
  silkscreen extent -0.85,-1.15 -0.75,-1.05, body extent -1,-0.85 1,0.85, height 0.55
VLS2520 [mm]
  rect 0.85x2 smd: 1(-0.825,0) 2(0.825,0)
  silkscreen extent -1.72,-0.05 -1.63,0.05, body extent -1.25,-1 1.25,1, height 1
W25N02KVZEIR [mm] "WSON-8  8X6MM"
  rect 0.95x0.45 smd: 1(-3.9,1.905) 2(-3.9,0.635) 3(-3.9,-0.635) 4(-3.9,-1.905) 5(3.9,-1.905) 6(3.9,-0.635) 7(3.9,0.635) 8(3.9,1.905)
  rect 3.45x4.35 smd: 9(0,0)
  silkscreen extent -4.57,-3 4,3, body extent -4.05,-3 4.05,3, height 0.8
XC6194B1NNER-G [mm]
  rect 0.25x0.25 smd mask+0.05: 1(-0.75,-0.85) 2(-0.25,-0.85) 3(0.25,-0.85) 4(0.75,-0.85) 5(0.75,0.85) 6(0.25,0.85) 7(-0.25,0.85) 8(-0.75,0.85)
  rect 1.8x1.04 smd mask+0.05: 9(0,0)
  silkscreen extent -1.45,-1 1.05,1, body extent -1,-1 1,1, height 0.33

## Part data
ANT1: "Antenna", Manufacturer_Name=AVX, Mouser Part Number=581-LSP69001299TR
C1 C2 C5 C6 C7 C8 C9 C10 C19 C29 C32 C33 C34 C35: library part C0603-100nF-X7R-50V, "Capacitor, Ceramic, 100nF, 0402, 10%, 50V, X7R", CASE=0402, Dielectric=X7R, Voltage=50V
C3 C4 C11 C12 C13 C14 C16 C18 C20 C22 C23 C24 C25 C28: library part C0603-10µF-X5R-6.3V, "Capacitor, Ceramic, 22µF, 0402, 20%, 6.3V, X5R", CASE=0402, Dielectric=X5R, Voltage=6.3V
C15 C17: "Capacitor", Manufacturer_Name=KEMET, Mouser Part Number=80-C1206C107M9P
C21: library part C0603-100nF-X7R-50V, "Capacitor, Ceramic, 1.2pF, 0603, +/-0.25pF, 50V", CASE=0603, Dielectric=COG, Voltage=50V
C26: library part C0603-100nF-X7R-50V, "Capacitor, Ceramic, 33pF, 0603, 5%, 50V, X7R", CASE=0603, Dielectric=X7R, Voltage=50V
C27: library part C0603-10µF-X5R-6.3V, "Capacitor, Ceramic, 15µF, 0402, 20%, 6.3V, X5R", CASE=0402, Dielectric=X5R, Voltage=6.3V
C30 C31: library part C0603-100nF-X7R-50V, "Capacitor, Ceramic, 6.8pF, 0402, 5%, 50V, COG", CASE=0402, Dielectric=COG, Voltage=50V
FB1: library part 5f30dd21d616792df468990f7003faa, "Chip Ferrite Bead, 0603, 100Ω @ 100MHz, 25%, 0.045Ω, 2A", Current Rating=2A, DC Resistance (DCR)=45mR, Manufacturer_Name=Murata, Max Operating Temperature=125°C, Min Operating Temperature=-55°C
J1 J2: "Header, 2-Pin"
J3: library part TC2030-MCP-NL-10, "Connector", Manufacturer_Name="Tag Connect"
L1 L2 L4 L5 L6: library part Inductor, "Wire Wound RF Inductor 20nH ±2% 370mA 0.27Ω 0402 (1005)", Manufacturer_Name=Murata
L3: library part Inductor, "Wire Wound RF Inductor 22nH ±2% 370mA 0.27Ω 0402 (1005)", Manufacturer_Name=Murata
L7: library part MURATA-1µH-4.3A-2.5x2x1.2, "SMD Power Inductor 1.76A, 0.042Ω, 10uH", DC Resistance="0.042Ω max.", Rated Current=1.76A
LED1: library part 150060VS75000, "LED", Manufacturer_Name=Vishay, Mouser Part Number=782-TLMS1100
Q1: library part 2N7002F, "Transistor Mosfet SI2302CDS-T1-GE3, 385mA canal N, SOT23", CASE=SOT23, Manufacturer_Name=NXP
R1 R2 R3 R4 R5 R6 R7 R8 R9 R10 R11 R12: library part R0603_120k_1%, "Resistor, Thin Film, 100k, 1%, 65mW, 0402", CASE=0402, Power=65mW, Tolerance=1%
U1 U4: library part TPS7A0212PDBVR, "Integrated Circuit", Manufacturer_Name="Texas Instruments", Mouser Part Number=595-TPS7A0212PDBVR
U2: "Integrated Circuit", Manufacturer_Name=U-Blox, Mouser Part Number=N/A
U3: "Integrated Circuit", Manufacturer_Name="Texas Instruments", Mouser Part Number=595-TXB0104RUTR
U5 U6 U13: "Integrated Circuit", Manufacturer_Name=Vishay, Mouser Part Number=781-SIP32431DR3-GE3
U7: "Integrated Circuit", Manufacturer_Name="Telit Wireless Solutions"
U8: "Integrated Circuit", Manufacturer_Name=Honeywell, Mouser Part Number=785-SM353LT
U9: library part ST4SI2M0020TPIFW, "Integrated Circuit", Manufacturer_Name=STMicroelectronics, Mouser Part Number=511-ST4SI2M0020TPIFW
U10 U11: "Integrated Circuit", Manufacturer_Name=Torex, Mouser Part Number=865-XC6194B1NNER-G
U12: "Integrated Circuit", Manufacturer_Name=E-PEAS, Manufacturer_Part_Number=aem10900
U14: "Integrated Circuit", Manufacturer_Name=STMicroelectronics, Mouser Part Number=511-STM32G0B1KEU6
U15: "Integrated Circuit", Manufacturer_Name=Winbond, Mouser Part Number=454-W25N02KVZEIR
U16: library part 7257f23b88fab88f30c8b27feb514af, "IMU ACCEL/GYRO I2C/SPI 14VFLGA", Manufacturer=STMicroelectronics, Max Supply Voltage=3.6V, Min Supply Voltage=1.62V, Operating Supply Current=9-900uA, Package=LGA-14-DM00249496, Temperature="-40°C to +85°C", Temperature Range High=+85°C, Temperature Range Low=-40°C
U17: "Integrated Circuit", Manufacturer_Name="Texas Instruments", Mouser Part Number=595-OPT3005DTSR
Y1: "Crystal or Oscillator", Manufacturer_Name=NDK, Mouser Part Number=344-NX3215SA32.768K3

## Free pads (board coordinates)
  round 1 smd far side paste-1 mask+0.5: 0(1.7,-48.1) 0(46,-20.5)
  round 1 smd paste-1 mask+0.5: 0(11.8,-47.7) 0(46,-24.3)

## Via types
v1: diameter 0.6, hole 0.3, Top Layer to Bottom Layer, 120 vias
v2: diameter 0.5, hole 0.2, Top Layer to Bottom Layer, 112 vias

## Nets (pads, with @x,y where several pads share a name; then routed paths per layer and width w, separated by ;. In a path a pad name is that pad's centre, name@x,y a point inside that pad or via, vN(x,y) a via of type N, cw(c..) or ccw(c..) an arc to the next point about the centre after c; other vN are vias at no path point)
+1V8: C4.2 C9.1 U1.5 U3.1 U3.12 U3.13 | length 11
  Top Layer w0.2: 24.741,-29.5 v1(24.425,-29.5) 24.875,-29.05 U3.12@25.7,-29.05 ; 24.766,-29.475 U3.13@25.5,-29.475 ; v1(25.05,-30.4) 25.583,-30.4 25.7,-30.283 U3.1@25.7,-29.7
  Bottom Layer w0.3: C4.2@20,-31.5 20.025,-31.525 21.353,-31.525 U1.5@21.378,-31.55 ; v1(25.05,-30.4) 25.107,-30.343 25.407,-30.343 26,-29.75 C9.1@26,-29.7
  Bottom Layer w0.5: U1.5@21.378,-31.55 21.407,-31.521 22.307,-31.521 22.6,-31.228 22.6,-30.223 23.343,-29.48 23.857,-29.48 ; 23.858,-29.481 24.406,-29.481 v1(24.425,-29.5)
+3V: C2.2 C12.2 C16.2 C20.2 C22.2 J3.1 R4.2 R5.2 U4.5 U6.4 U10.1 U11.1 U14.4 | length 90.5
  Top Layer w0.15: v2(26.1,-19.9) 26.125,-19.925 26.125,-20.825 U14.4@26.15,-20.85
  Top Layer w0.3: v1(34.6,-22.8) 34.657,-22.743 34.657,-22.618 35.15,-22.125 U6.4@35.15,-21.75
  Top Layer w0.5: J3.1@14.43,-22.135 14.485,-22.19 14.485,-22.585 v1@15.081,-23.181
  Int4 (PWR) w0.5: v1(15.1,-23.2) 16.183,-22.117 16.183,-19.367 16.75,-18.8 18.6,-18.8 19.98,-20.18 23.905,-20.18 24.575,-20.85 26.15,-20.85 ; v2(26.1,-19.9) 26.1,-20.8 26.15,-20.85 ; v1(31.6,-43) 32.3,-43 33.8,-44.5 39.244,-44.5 39.776,-43.968 39.776,-43.276 37.5,-41 33.738,-41 33.267,-40.529 33.267,-29.414 ; v1@34.6,-22.773 34.6,-20.673 34.307,-20.38 31.8,-20.38 ; v1(37.5,-26.9) 37.5,-28.078 36.178,-29.4 33.281,-29.4 33.267,-29.414 ; 26.15,-20.85 27.85,-20.85 28.32,-20.38 31.8,-20.38 ; 31.8,-20.38 31.8,-22.714 32.27,-23.184 32.27,-25.72 32.93,-26.38 32.93,-28.25 32.83,-28.35 32.83,-28.978 33.267,-29.414
  Bottom Layer w0.15: v2(26.1,-19.9) 26.1,-19.972 26.4,-20.272 C2.2@26.4,-20.8
  Bottom Layer w0.2: U10.1@34.35,-27.95 34.375,-27.975 35.35,-27.975 C20.2@35.4,-28.025 R4.2@36.6,-28.025 36.65,-28.025 37.5,-27.175 v1(37.5,-26.9) ; U11.1@34.35,-25.05 34.375,-25.075 C22.2@35.375,-25.075 ; C22.2@35.4,-25.1 R5.2@36.6,-25.1
  Bottom Layer w0.3: C16.2@35.3,-21.75 35.3,-21.8 34.657,-22.443 34.657,-22.743 v1(34.6,-22.8) 34.6,-23.803 35.35,-24.553 35.35,-25.05 C22.2@35.4,-25.1
  Bottom Layer w0.5: U4.5@29.278,-45.75 29.278,-44.676 29.904,-44.05 29.904,-43.312 30.197,-43.019 31.581,-43.019 v1(31.6,-43)
+3V_BKP_GPS: C5.2 C23.2 U2.3 U10.8 | length 26.1
  Top Layer w0.5: v1(38.675,-43.675) 38.675,-41.925 U2.3@38.7,-41.9
  Int4 (PWR) w0.5: v2(32.3,-27.2) 32.14,-27.36 32.14,-29.414 32.372,-29.645 32.372,-29.648 32.647,-29.923 32.647,-41.047 33.3,-41.7 36.7,-41.7 v1(38.675,-43.675)
  Bottom Layer w0.2: C23.2@31.637,-27.963 32.637,-27.963 U10.8@32.65,-27.95 ; C23.2@31.647,-27.975 31.797,-27.825 31.797,-27.625 32.222,-27.2 v2(32.3,-27.2)
  Bottom Layer w0.5: v1(38.675,-43.675) 38.675,-43.648 38.7,-43.623 C5.2@38.7,-42.7
+3V_CUT: C3.2 C10.2 C18.2 C33.2 U1.1 U3.11 U6.1 U15.3 U15.7 U15.8 | length 73
  Top Layer w0.2: v1(24.8,-28.4) U3.11@25.7,-28.4
  Top Layer w0.3: U6.1@36.45,-19.85 36.5,-19.8 v1(37.3,-19.8)
  Top Layer w0.5: v1(12.2,-26.3) 12.8,-26.9 C33.2@13.3,-26.9
  Int4 (PWR) w0.5: v1(12.2,-26.3) 12.219,-26.281 13.112,-26.281 13.293,-26.1 14,-26.1 ; v1(22.2,-27.3) 22.2,-28.4 ; v1(26.2,-31.5) 26.2,-28.693 25.907,-28.4 v1(24.8,-28.4) 22.4,-28.4 22.2,-28.4 ; v1(37.3,-19.8) 36.6,-19.1 36.6,-18.293 36.307,-18 26.4,-18 25.68,-18.72 23.92,-18.72 22.18,-16.98 13.02,-16.98 12.56,-17.44 12.56,-18.76 14.43,-20.63 14.43,-21.982 13.7,-22.712 13.7,-24.1 14,-24.4 14,-26.1 ; 14,-26.1 14,-30.307 14.293,-30.6 20,-30.6 22.2,-28.4
  Bottom Layer w0.3: v1(12.2,-26.3) 12.218,-26.283 13.182,-26.283 U15.3@13.2,-26.265 ; U15.8@21,-28.805 21.995,-28.805 22.2,-28.6 v1(22.2,-27.3) 21.965,-27.535 U15.7@21,-27.535 ; U1.1@23.822,-31.55 23.847,-31.525 25.275,-31.525 C3.2@25.3,-31.5 v1(26.2,-31.5) ; v1(24.8,-28.4) C10.2@26,-28.4 ; C18.2@36.3,-19.85 37.25,-19.85 v1(37.3,-19.8)
+3V_SENSORS: C1.2 C6.2 C24.2 C34.2 C35.2 R12.2 U2.2 U2.17 U11.8 U16.5 U16.8 U17.1 | length 82.1
  Top Layer w0.3: v1(13.313,-17.987) 13.313,-16.676 13.489,-16.5 C35.2@14.3,-16.5 14.313,-16.487 14.873,-16.487 15.11,-16.25 U17.1@15.95,-16.25 ; v1(14.8,-27) 14.9,-26.9 15.95,-26.9 16.05,-26.8 16.05,-26.75 16.3,-26.5 U16.5@17.587,-26.5 ; U16.8@17.75,-28.162 17.775,-28.188 17.775,-29.775 v1(17.8,-29.8) ; v1(19.3,-18.3) R12.2@19.3,-17.5
  Top Layer w0.5: v1(30.4,-33.3) 30.427,-33.3 30.527,-33.4 U2.17@32.1,-33.4 ; v1(36.8,-43.65) U2.2@36.8,-41.9
  Int4 (PWR) w0.5: v1(13.313,-17.987) 13.34,-17.987 13.545,-17.782 15.223,-17.782 15.306,-17.866 ; v1(17.8,-29.8) 15.4,-29.8 14.8,-29.2 v1(14.8,-27) 14.8,-24.089 ; v1(19.3,-18.3) 19.273,-18.3 18.755,-17.782 15.39,-17.782 15.306,-17.866 ; v1(30.4,-33.3) 31.571,-33.3 31.864,-33.007 ; v1(36.8,-43.65) 35.6,-42.45 33.15,-42.45 31.864,-41.164 31.864,-33.007 ; 14.8,-24.089 18.311,-24.089 20.82,-21.58 22.121,-21.58 23.521,-22.98 28.362,-22.98 28.722,-22.62 29.82,-22.62 31.319,-24.119 31.319,-24.644 31.52,-24.845 31.52,-29.67 31.752,-29.902 31.752,-29.904 31.864,-30.016 31.864,-33.007 ; 14.8,-24.089 14.43,-23.719 14.43,-22.922 15.306,-22.046 15.306,-17.866
  Bottom Layer w0.15: C24.2@31.6,-25.1 31.65,-25.05 U11.8@32.65,-25.05
  Bottom Layer w0.3: v1(31.3,-24.1) 31.3,-24.114 31.6,-24.414 C24.2@31.6,-25.1
  Bottom Layer w0.5: v1(30.4,-33.3) 30.427,-33.3 30.577,-33.15 C1.2@31.177,-33.15 ; v1(36.8,-43.65) C6.2@36.8,-42.9
ANT: C26.2 L4.2 U7.A5 | length 5
  Top Layer w0.278: C26.2@11.2,-39 11.228,-39.028 11.228,-40.372 L4.2@11.255,-40.4 11.255,-41.256 11.5,-41.5 U7.A5@13.9,-41.5
CS_FLASH: U14.32 U15.1 | length 26
  Top Layer w0.15: U14.32@28.35,-21.55 28.375,-21.525 29.375,-21.525 v2(29.4,-21.5)
  Bottom Layer w0.15: U15.1@13.2,-28.805 13.896,-28.805 14,-28.909 14,-30.307 14.293,-30.6 20.2,-30.6 20.7,-30.1 21.5,-30.1 23.63,-27.97 23.995,-27.97 24.359,-27.605 24.359,-27.039 23.9,-26.579 23.9,-22.99 24.1,-22.79 28.11,-22.79 v2(29.4,-21.5)
CTS1V8: U3.5 U7.AA17 | length 5.5
  Top Layer w0.15: U7.AA17@27.1,-34.3 27.137,-34.263 27.137,-33.863 28.3,-32.7 28.3,-31.3 27.3,-30.3 U3.5@27.3,-29.7
GND: C1.1 C2.1 C3.1 C4.1 C5.1 C6.1 C7.1 C8.1 C9.2 C10.1 C11.1 C12.1 C13.1 C14.1 C15.1 C16.1 C17.1 C18.1 C19.1 C20.1 C22.1 C23.1 C24.1 C25.1 C27.1 C28.1 C29.1 C30.2 C31.2 C32.2 C33.1 C34.1 C35.1 J1.2 J2.2 J3.6 L1.1 L2.1 L3.1 L4.1 L5.1 L6.1 LED1.1 Q1.2 R1.1 R2.1 R3.1 R6.1 R7.1 R9.1 R10.2 U1.2 U2.1 U2.4 U2.5 U2.6 U2.10 U2.11 U2.15 U2.16 U2.20 U2.21 U3.6 U4.2 U5.2 U5.5 U6.2 U6.5 U7.A3 U7.A7 U7.A9 U7.A13 U7.A17 U7.B4 U7.B6 U7.B10 U7.B12 U7.B14 U7.B16 U7.C19 U7.D18 U7.F8 U7.F12 U7.F18 U7.G19 U7.H6 U7.H14 U7.J19 U7.K18 U7.M18 U7.N19 U7.P6 U7.P14 U7.T8 U7.T12 U7.U1 U7.V2 U7.W19 U7.Y2 U7.Y4 U8.3 U9.1 U9.9 U10.2 U10.5 U10.6 U10.9 U11.2 U11.5 U11.6 U11.9 U12.3 U12.7 U12.8 U12.11 U12.13 U12.20 U12.21 U12.24 U12.27 U12.29 U13.2 U13.5 U14.5 U14.33 U15.4 U15.9 U16.2 U16.3 U16.6 U16.7 U17.2 U17.4 | length 163.4
  Top Layer w0.15: v2(25.3,-19.9) 25.395,-19.9 25.645,-20.15 25.65,-20.15 U14.5@25.65,-20.85
  Top Layer w0.2: L6.1@12.044,-36.3 12.044,-36.2 12.744,-36.2 13,-36.456 v2(13,-36.5) 13.2,-36.7 U7.A13@13.9,-36.7 ; L5.1@12.044,-34.7 12.883,-34.7 12.923,-34.659 12.923,-34.377 v1(13,-34.3) U7.A17@13.9,-34.3 ; L3.1@12.044,-30.9 13.233,-30.9 13.433,-31.1 v2(13.5,-31.1) ; L1.1@12.294,-42.55 L1.1@12.144,-42.7 v2(13,-42.7) U7.A3@13.9,-42.7 U7.A3@14.1,-42.5 ; v2(13,-40.3) U7.A7@13.9,-40.3 14.5,-40.3 ; v2(13,-39.1) U7.A9@13.9,-39.1 ; v2(13,-35.4) v2@13,-35.356 ; 14.5,-37.3 U7.B12@15.1,-37.3 ; 14.5,-36.1 U7.B14@15.1,-36.1 ; 14.5,-34.9 U7.B16@15.1,-34.9 ; U7.C19@15.7,-32.5 v1(15.7,-31.5) ; U7.D18@16.3,-33.7 16.3,-33.1 ; U7.F8@17.5,-39.7 v2(18.3,-39.7) ; U7.F12@17.5,-37.3 v2(18.7,-37.3) ; U7.F18@17.5,-33.7 17.5,-33.1 ; v2(17.8,-36.1) U7.H14@18.7,-36.1 ; U7.G19@18.1,-32.5 v1(18.1,-31.5) ; U7.H6@18.7,-40.9 v2(19.6,-40.9) ; v1(19,-31.5) 19.1,-31.5 19.3,-31.7 U7.J19@19.3,-32.5 ; U7.K18@19.9,-33.7 19.9,-33.1 ; U7.M18@21.1,-33.7 21.1,-33.1 U7.N19@21.7,-32.5 21.7,-31.854 21.1,-31.254 v2(21.1,-30.6) ; U7.P6@22.3,-40.9 v2(23.475,-40.9) 23.475,-39.725 U7.T8@23.5,-39.7 ; U7.P14@22.3,-36.1 23.364,-36.1 23.464,-36.2 v2(23.545,-36.2) ; U7.T12@23.5,-37.3 v2@23.5,-36.245 ; U3.6@27.3,-29.05 27.983,-29.05 28.1,-28.933 v1(28.1,-28.4) ; U2.15@34.9,-28.7 34.9,-27.4 v1(35.4,-26.9) ; v2(36.6,-23.8) 36.681,-23.8 36.781,-23.9 U12.11@38.05,-23.9 ; v2(37.3,-25.5) 37.25,-25.45 37.25,-24.85 37.4,-24.7 U12.13@38.05,-24.7 ; U12.8@38.05,-22.7 38.05,-21.95 v2(38,-21.9) 38.8,-21.9 U12.7@38.8,-21.95 ; U12.3@40.4,-21.95 40.4,-21.3 v2(40.9,-20.8) ; U12.20@40.8,-25.85 40.8,-26.6 v2(41.2,-27) ; v2@41.2,-26.95 U12.21@41.2,-25.85 ; U12.24@41.95,-24.3 42.635,-24.3 42.735,-24.4 v2(43.7,-24.4) ; U12.27@41.95,-23.1 43.4,-23.1 v2(43.7,-23.4)
  Top Layer w0.3: L2.1@12.044,-28.4 12.9,-28.4 13.1,-28.6 v2(13.1,-29.5) ; L4.1@12.144,-40.4 12.846,-40.4 12.946,-40.3 v2(13,-40.3) ; v1(14.309,-18.452) 14.3,-18.443 C35.1@14.3,-17.5 15.2,-17.5 15.265,-17.565 ; U17.4@15.95,-17.75 15.45,-17.75 15.265,-17.565 ; U17.2@15.95,-16.75 15.441,-16.75 15.265,-16.926 15.265,-17.565 ; v1(20.1,-29.3) 20.157,-29.243 20.325,-29.243 Q1.2@21.184,-28.384 ; C32.2@23.8,-18.1 23.825,-18.075 23.825,-16.825 LED1.1@23.85,-16.8 v2(24.8,-16.8) ; 24.7,-43.9 U7.V2@24.7,-43.3 24.7,-42.705 24.967,-42.438 25.062,-42.438 v2(25.1,-42.4) ; v2@25.138,-42.538 25.138,-42.438 v2(25.1,-42.4) ; U7.W19@25.3,-32.5 v1(26.2,-32.5) ; U7.Y4@25.9,-42.1 25.4,-42.1 v2(25.1,-42.4) ; v2(26.8,-16.1) C31.2@26.8,-16.8 C30.2@27.8,-16.8 v2(27.8,-16.1) ; C29.1@30.075,-16.825 30.075,-16.125 v2(30.1,-16.1) ; v2(30.5,-39.9) 30.538,-39.862 30.538,-39.262 30.7,-39.1 U2.20@32.1,-39.1 ; v1(30.5,-31.5) U2.16@32.1,-31.5 ; v2(31.2,-16.1) 31.25,-16.15 R9.1@31.25,-16.825 ; v1(33.5,-22.1) 33.557,-22.043 33.557,-21.668 33.9,-21.325 R3.1@33.95,-21.325 ; U13.2@33.95,-17.4 U13.5@35.85,-17.4 35.893,-17.357 36.618,-17.357 36.957,-17.018 37.357,-17.018 C28.1@37.45,-16.925 38.275,-16.925 v1(38.3,-16.9) ; v1(34.3,-46.7) 34.309,-46.709 36.599,-46.709 C19.1@36.608,-46.718 ; v1(34.9,-43.6) U2.1@34.9,-41.9 ; U6.5@35.8,-21.75 35.85,-21.8 35.85,-22.569 36.2,-22.919 v1(36.2,-23) ; U6.2@35.8,-19.85 v1(35.8,-18.8) ; v1(40.6,-43.625) U2.4@40.6,-41.9 ; v2(43.7,-23.4) 43.738,-23.362 44.363,-23.362 45.05,-22.674 45.05,-21.9 J2.2@45.55,-21.4 ; U2.6@45.3,-39.1 v2(46.7,-39.1) ; U2.10@45.3,-31.5 45.3,-28.881 45.4,-28.781 v1(45.4,-28.7)
  Top Layer w0.5: v1(12.5,-24.1) 13.3,-24.9 C33.1@13.3,-25.9 ; J3.6@16.97,-20.865 16.97,-19.73 v2(17,-19.7) ; U2.11@42.5,-28.7 v1(45.4,-28.7) ; v1(42.6,-43.625) U2.5@42.6,-41.9
  Bottom Layer w0.15: v2(25.3,-19.9) 25.3,-20.7 C2.1@25.4,-20.8 ; v2(27.3,-24.7) 27.3,-24.3 27.675,-23.925 R10.2@28.35,-23.925 ; v2(30.4,-29.7) 30.4,-29.05 R6.1@30.475,-28.975 C23.1@31.625,-28.975 ; U10.5@32.65,-29.45 32.25,-29.45 32.1,-29.6 31.8,-29.6 31.625,-29.425 C23.1@31.625,-28.975 ; U10.6@32.65,-28.95 31.65,-28.95 C23.1@31.625,-28.975
  Bottom Layer w0.2: 14.8,-26.4 16.6,-26.4 U15.9@17.1,-26.9 ; v1(19,-31.5) 19,-32.2 19.3,-32.5 C4.1@20,-32.5 ; C8.1@19.6,-41.8 v2(19.6,-40.9) ; v1(21.5,-48.2) v1(21.5,-47.082) U9.9@21.5,-45.5 ; C15.1@21.7,-36.776 21.3,-36.376 v2(21.3,-35.75) 21.357,-35.693 21.357,-35.243 21.6,-35 R1.1@22.1,-35 ; R7.1@30.4,-26.1 R7.1@30.408,-26.1 ; R7.1@30.558,-26.25 R7.1@30.408,-26.1 ; v2(30.9,-26.8) 30.957,-26.743 30.957,-26.517 31,-26.474 31,-26.1 ; U11.5@32.65,-26.55 32.625,-26.575 32.325,-26.575 32.2,-26.7 31.717,-26.7 31.6,-26.583 C24.1@31.6,-26.1 ; U11.6@32.65,-26.05 32.625,-26.075 31.625,-26.075 C24.1@31.6,-26.1 ; v1(33.5,-28.7) 33.6,-28.6 33.6,-25.9 v1(33.5,-25.8) ; U10.2@34.35,-28.45 34.775,-28.45 35.35,-29.025 C20.1@35.4,-29.025 35.963,-29.025 36.08,-28.908 36.08,-28.684 36.239,-28.525 36.961,-28.525 38.5,-26.986 v1(38.5,-26.9) ; U11.2@34.35,-25.55 34.8,-25.55 35.35,-26.1 C22.1@35.4,-26.1 v1(35.4,-26.9) ; v2(37.3,-25.5) 37.35,-25.45 37.35,-24.95 38,-24.3 C25.1@38.05,-24.3 ; C27.1@40.8,-21.95 40.85,-21.9 40.85,-20.85 v2(40.9,-20.8) ; R7.1@30.408,-26.1 31,-26.1 ; 31,-26.1 C24.1@31.6,-26.1
  Bottom Layer w0.3: v2(23.475,-40.9) 23.529,-40.9 23.953,-40.476 23.976,-40.476 C17.1@23.976,-39.2 ; U1.2@23.822,-32.5 C3.1@25.3,-32.5 v1(26.2,-32.5) ; U9.1@24.385,-43.595 24.385,-42.691 24.637,-42.438 25.062,-42.438 v2(25.1,-42.4) ; v2(25,-35.5) 26.1,-36.6 R2.1@27.1,-36.6 ; C9.2@27,-29.7 v1(27.894,-29.7) ; C10.1@27,-28.4 v1(28.1,-28.4) ; R2.1@27.25,-36.475 27.525,-36.2 U5.2@28.55,-36.2 ; v1(28.8,-34.5) C13.1@29.5,-34.5 ; C7.1@29.7,-39.9 v2(30.5,-39.9) ; C14.1@29.7,-38 v2(30.5,-38) ; v1(34.9,-43.6) 34.9,-43.1 35.1,-42.9 C6.1@35.8,-42.9 ; C18.1@35.3,-19.85 35.3,-19.275 35.325,-19.275 v1(35.8,-18.8) ; U8.3@36.1,-45.984 36.1,-44.4 ; v1(36.2,-23) 36.2,-22.919 36.3,-22.819 C16.1@36.3,-21.75 ; C5.1@39.7,-42.7 39.8,-42.7 40.4,-42.7 40.6,-42.9 v1(40.6,-43.625) ; v1(45.4,-28.7) 45.4,-28.781 45.6,-28.981 45.6,-31.3
  Bottom Layer w0.5: v1(12.5,-24.1) 12.519,-24.119 12.519,-24.514 13,-24.995 U15.4@13.2,-24.995 ; v1(30.5,-31.5) 30.527,-31.5 C1.1@31.177,-32.15 ; C12.1@30.904,-44 v1(31.9,-44) ; U4.2@31.722,-46.7 C11.1@33.329,-46.7 v1(34.3,-46.7)
  other v1: 17.75,-48.9 33.9,-48.9 13.5,-48.875 22,-48.875 25.75,-48.875 30.25,-48.875 38.4,-47.9 16.25,-47.5 26.25,-47.25 20.3,-47.1 22.7,-47 40.9,-46.7 14.25,-46.5 28.1,-46.2 43.375,-46.15 12.5,-45.6 21.2,-45.6 46,-45.25 28.75,-43 46.7,-41.8 28.7,-41.3 34,-40 37,-40 40,-40 43,-40 20,-39.75 18.75,-38.5 21.25,-38.5 22.25,-38.5 20,-38 34,-37.5 37,-37.5 40,-37.5 43,-37.5 20,-36.5 34,-34.5 37,-34.5 40,-34.5 43,-34.5 13,-32.75 16.9,-31.5 34,-31.5 37,-31.5 40,-31.5 43,-31.5 15.8,-28.6 17,-28.6 33.6,-27.2 43.7,-26.5 46,-26.5 15.9,-25.4 16.9,-25.4 39.1,-24.9 40.9,-24.8 40,-23.9 39.1,-23 40.9,-23 42.3,-19.1 43.75,-18.25 40.75,-17.25 37,-16 12.6,-15.7 15.2,-15.6 21,-15.6 23.2,-15.6 29,-15.6 32.3,-15.6 35.3,-15.6
  other v2: 16.3,-45.7 12.9,-44.1 16.1,-41.2 24.6,-41.2 17.4,-38.5 13,-37.4 46.8,-37.1 16.1,-35.8 28.6,-26.2 19.3,-24.9 24.5,-24.7 25.9,-24.7 24.6,-23.6 25.9,-23.6 27.3,-23.6 24.6,-22.2 25.9,-22.2 27.3,-22.2 30.8,-21.2
NetANT1_3: ANT1.3 L1.2 | length 9.7
  Top Layer w0.278: ANT1.3@7.7,-36.15 9.25,-36.15 9.8,-36.7 9.8,-42.5 10,-42.7 L1.2@11.255,-42.7
NetANT1_4: ANT1.4 C21.1 L3.2 | length 5.4
  Top Layer w0.278: ANT1.4@7.7,-32.25 9.05,-30.9 L3.2@11.155,-30.9 11.155,-32.256 C21.1@11.2,-32.3
NetANT1_5: ANT1.5 L2.2 | length 3.5
  Top Layer w0.278: ANT1.5@7.7,-28.35 7.75,-28.4 L2.2@11.155,-28.4
NetC15_2: C15.2 U7.N4 | length 2.6
  Top Layer w0.15: v2(21.35,-41.15) 21.7,-41.5 U7.N4@21.7,-42.1
  Bottom Layer w0.15: v2(21.35,-41.15) 21.35,-40.174 C15.2@21.7,-39.824
NetC21_2: C21.2 C26.1 L5.2 L6.2 | length 4.7
  Top Layer w0.278: C26.1@11.2,-38 11.155,-37.955 L6.2@11.155,-36.3 L5.2@11.155,-34.7 11.155,-34.012 11.2,-33.967 C21.2@11.2,-33.3
NetC27_2: C27.2 U12.4 | length 2.5
  Top Layer w0.2: U12.4@40,-21.95 40,-21 v2(40.2,-20.8)
  Bottom Layer w0.2: C27.2@39.8,-21.95 39.8,-21.2 v2(40.2,-20.8)
NetC30_1: C30.1 U14.2 Y1.2 | length 4.7
  Top Layer w0.15: U14.2@27.15,-20.85 27.15,-19.65 27.4,-19.4 28.05,-19.4 28.125,-19.325 28.125,-18.925 Y1.2@28.55,-18.5 C30.1@28.55,-17.1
